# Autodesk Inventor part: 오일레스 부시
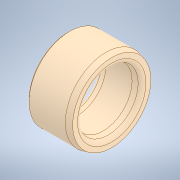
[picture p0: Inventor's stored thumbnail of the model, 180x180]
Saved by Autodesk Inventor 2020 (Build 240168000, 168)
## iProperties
Created: 2024-05
Part Number: 오일레스 부시
Material: 구리, 합금
Document SubType Name: Modeling
Designer: oem
Density: 8.92 g/cm^3
Appearance: 기본값
Author: jhkim
Sending System: Autodesk Inventor 2025
Preprocessor: ST-DEVELOPER v20
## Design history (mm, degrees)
feature "솔리드1"
node "솔리드2"
